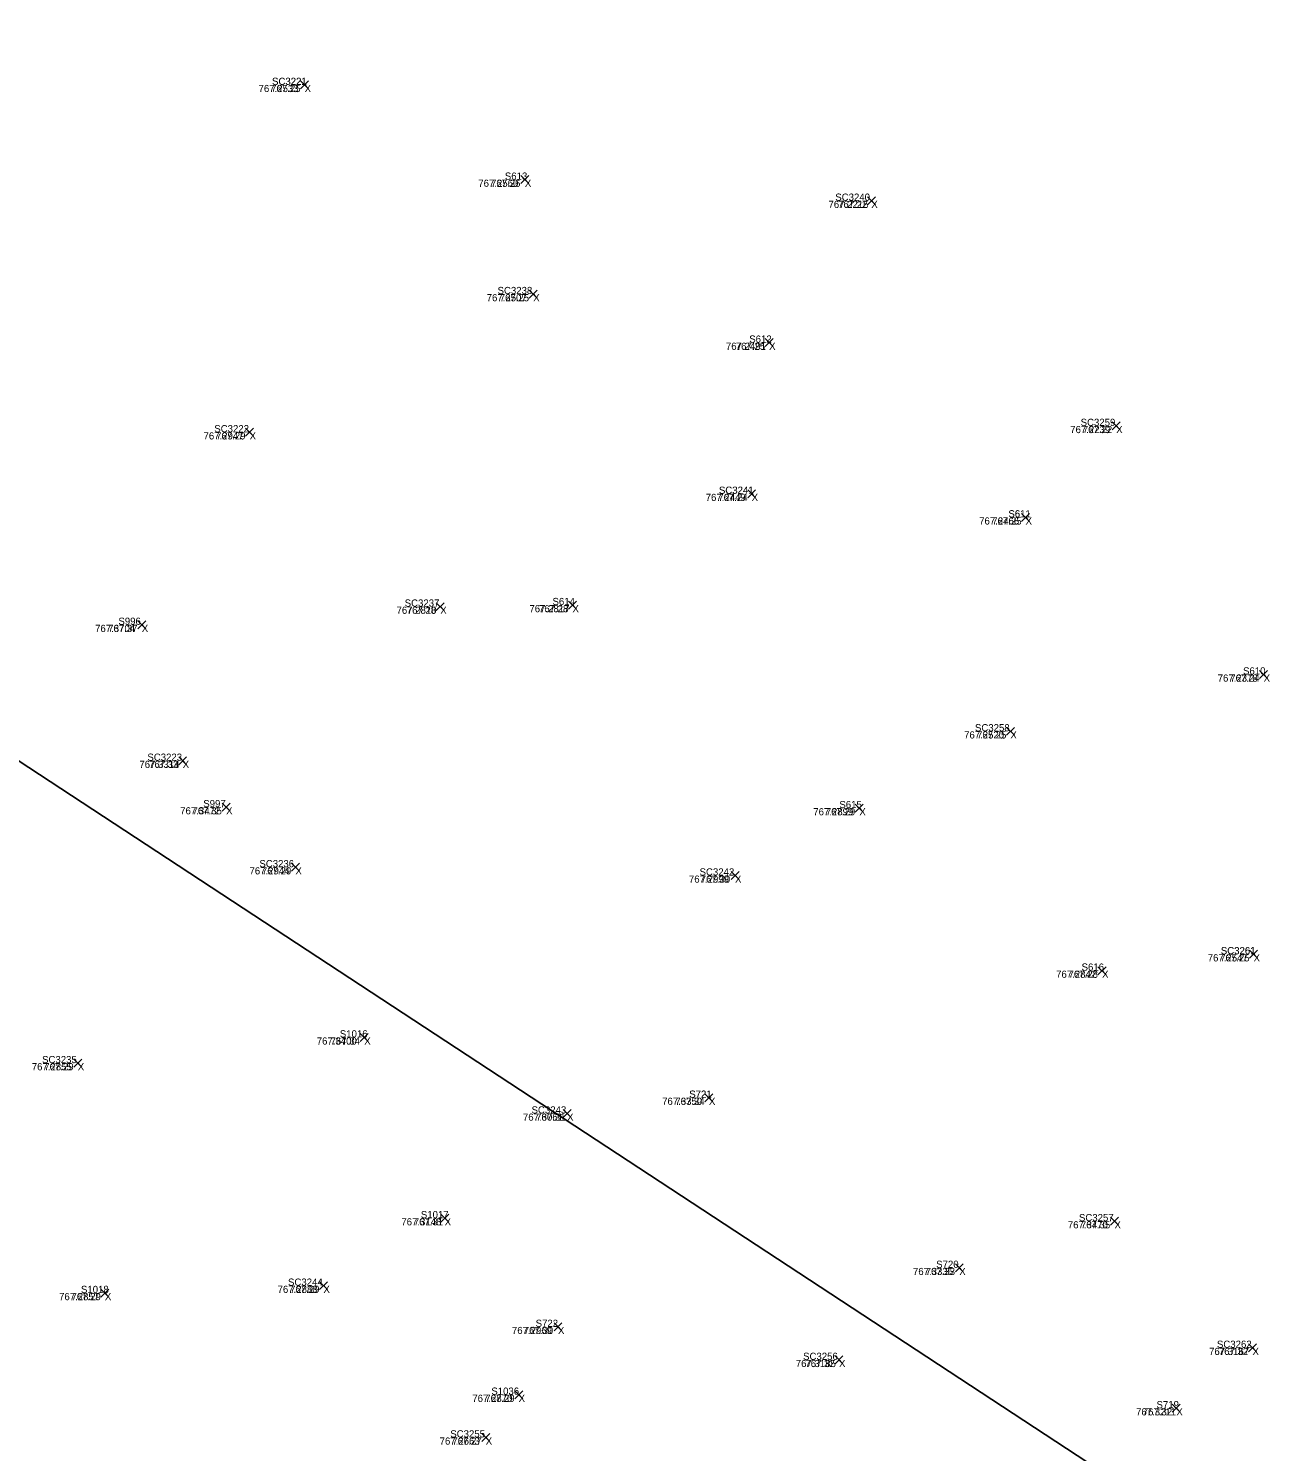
# Model space of a CAD drawing. Extents: x 1845019 to 1877956, y 680444 to 701081.
# Drawn here: x 1857714.75 to 1857725.26, y 694240.65 to 694252.54 of the extents above; entities that cross this region are included whole.
import ezdxf

# ---------------------------------------------------------------- set-up
doc = ezdxf.new("R2010")
doc.units = 0
for name, color, linetype in [('SV_X_CL_Survey_20', 7, 'Continuous'), ('SV_X_Random_Point', 7, 'Continuous'), ('SV_X_Text_Comment', 7, 'Continuous'), ('SV_X_Text_Elevation', 7, 'Continuous'), ('SV_X_Text_Name', 7, 'Continuous')]:
    doc.layers.add(name, color=color, linetype=linetype)

msp = doc.modelspace()

# ---------------------------------------------------------------- linework, layer by layer
at = {"layer": 'SV_X_CL_Survey_20'}
msp.add_line((1856038.267, 695346.314), (1858797.327, 693536.085), dxfattribs=at)
at = {"layer": 'SV_X_Random_Point'}
for p, q in [((1857717.021, 694252.038), (1857717.088, 694252.105)), ((1857717.021, 694252.105), (1857717.088, 694252.038)), ((1857717.021, 694252.038), (1857717.088, 694252.105)), ((1857717.021, 694252.105), (1857717.088, 694252.038)), ((1857718.862, 694251.247), (1857718.928, 694251.314)), ((1857718.862, 694251.314), (1857718.928, 694251.247)), ((1857718.862, 694251.247), (1857718.928, 694251.314)), ((1857718.862, 694251.314), (1857718.928, 694251.247)), ((1857721.757, 694251.071), (1857721.824, 694251.137)), ((1857721.757, 694251.137), (1857721.824, 694251.071)), ((1857721.757, 694251.071), (1857721.824, 694251.137)), ((1857721.757, 694251.137), (1857721.824, 694251.071)), ((1857718.931, 694250.29), (1857718.998, 694250.357)), ((1857718.931, 694250.357), (1857718.998, 694250.29)), ((1857718.931, 694250.29), (1857718.998, 694250.357)), ((1857718.931, 694250.357), (1857718.998, 694250.29)), ((1857720.903, 694249.885), (1857720.969, 694249.952)), ((1857720.903, 694249.952), (1857720.969, 694249.885)), ((1857720.903, 694249.885), (1857720.969, 694249.952)), ((1857720.903, 694249.952), (1857720.969, 694249.885)), ((1857716.561, 694249.136), (1857716.628, 694249.203)), ((1857716.561, 694249.203), (1857716.628, 694249.136)), ((1857716.561, 694249.136), (1857716.628, 694249.203)), ((1857716.561, 694249.203), (1857716.628, 694249.136)), ((1857723.802, 694249.189), (1857723.869, 694249.255)), ((1857723.802, 694249.255), (1857723.869, 694249.189)), ((1857723.802, 694249.189), (1857723.869, 694249.255)), ((1857723.802, 694249.255), (1857723.869, 694249.189)), ((1857720.757, 694248.621), (1857720.823, 694248.688)), ((1857720.757, 694248.688), (1857720.823, 694248.621)), ((1857720.757, 694248.621), (1857720.823, 694248.688)), ((1857720.757, 694248.688), (1857720.823, 694248.621)), ((1857723.046, 694248.424), (1857723.113, 694248.491)), ((1857723.046, 694248.491), (1857723.113, 694248.424)), ((1857723.046, 694248.424), (1857723.113, 694248.491)), ((1857723.046, 694248.491), (1857723.113, 694248.424)), ((1857718.155, 694247.679), (1857718.221, 694247.745)), ((1857718.155, 694247.745), (1857718.221, 694247.679)), ((1857718.155, 694247.679), (1857718.221, 694247.745)), ((1857718.155, 694247.745), (1857718.221, 694247.679)), ((1857719.259, 694247.692), (1857719.326, 694247.759)), ((1857719.259, 694247.759), (1857719.326, 694247.692)), ((1857719.259, 694247.692), (1857719.326, 694247.759)), ((1857719.259, 694247.759), (1857719.326, 694247.692)), ((1857715.66, 694247.527), (1857715.727, 694247.594)), ((1857715.66, 694247.594), (1857715.727, 694247.527)), ((1857715.66, 694247.527), (1857715.727, 694247.594)), ((1857715.66, 694247.594), (1857715.727, 694247.527)), ((1857725.034, 694247.112), (1857725.101, 694247.178)), ((1857725.034, 694247.178), (1857725.101, 694247.112)), ((1857725.034, 694247.112), (1857725.101, 694247.178)), ((1857725.034, 694247.178), (1857725.101, 694247.112)), ((1857722.919, 694246.637), (1857722.986, 694246.703)), ((1857722.919, 694246.703), (1857722.986, 694246.637)), ((1857722.919, 694246.637), (1857722.986, 694246.703)), ((1857722.919, 694246.703), (1857722.986, 694246.637)), ((1857716.003, 694246.39), (1857716.069, 694246.457)), ((1857716.003, 694246.457), (1857716.069, 694246.39)), ((1857716.003, 694246.39), (1857716.069, 694246.457)), ((1857716.003, 694246.457), (1857716.069, 694246.39)), ((1857716.366, 694246.002), (1857716.433, 694246.069)), ((1857716.366, 694246.069), (1857716.433, 694246.002)), ((1857716.366, 694246.002), (1857716.433, 694246.069)), ((1857716.366, 694246.069), (1857716.433, 694246.002)), ((1857721.656, 694245.995), (1857721.723, 694246.062)), ((1857721.656, 694246.062), (1857721.723, 694245.995)), ((1857721.656, 694245.995), (1857721.723, 694246.062)), ((1857721.656, 694246.062), (1857721.723, 694245.995)), ((1857716.944, 694245.5), (1857717.011, 694245.567)), ((1857716.944, 694245.567), (1857717.011, 694245.5)), ((1857716.944, 694245.5), (1857717.011, 694245.567)), ((1857716.944, 694245.567), (1857717.011, 694245.5)), ((1857720.618, 694245.431), (1857720.685, 694245.498)), ((1857720.618, 694245.498), (1857720.685, 694245.431)), ((1857720.618, 694245.431), (1857720.685, 694245.498)), ((1857720.618, 694245.498), (1857720.685, 694245.431)), ((1857724.951, 694244.773), (1857725.018, 694244.84)), ((1857724.951, 694244.84), (1857725.018, 694244.773)), ((1857724.951, 694244.773), (1857725.018, 694244.84)), ((1857724.951, 694244.84), (1857725.018, 694244.773)), ((1857723.684, 694244.636), (1857723.751, 694244.703)), ((1857723.684, 694244.703), (1857723.751, 694244.636)), ((1857723.684, 694244.636), (1857723.751, 694244.703)), ((1857723.684, 694244.703), (1857723.751, 694244.636)), ((1857717.519, 694244.079), (1857717.586, 694244.146)), ((1857717.519, 694244.146), (1857717.586, 694244.079)), ((1857717.519, 694244.079), (1857717.586, 694244.146)), ((1857717.519, 694244.146), (1857717.586, 694244.079)), ((1857715.125, 694243.864), (1857715.192, 694243.93)), ((1857715.125, 694243.93), (1857715.192, 694243.864)), ((1857715.125, 694243.864), (1857715.192, 694243.93)), ((1857715.125, 694243.93), (1857715.192, 694243.864)), ((1857720.399, 694243.575), (1857720.466, 694243.641)), ((1857720.399, 694243.641), (1857720.466, 694243.575)), ((1857720.399, 694243.575), (1857720.466, 694243.641)), ((1857720.399, 694243.641), (1857720.466, 694243.575)), ((1857719.214, 694243.443), (1857719.281, 694243.51)), ((1857719.214, 694243.51), (1857719.281, 694243.443)), ((1857719.214, 694243.443), (1857719.281, 694243.51)), ((1857719.214, 694243.51), (1857719.281, 694243.443)), ((1857718.192, 694242.568), (1857718.259, 694242.634)), ((1857718.192, 694242.634), (1857718.259, 694242.568)), ((1857718.192, 694242.568), (1857718.259, 694242.634)), ((1857718.192, 694242.634), (1857718.259, 694242.568)), ((1857723.788, 694242.542), (1857723.855, 694242.609)), ((1857723.788, 694242.609), (1857723.855, 694242.542)), ((1857723.788, 694242.542), (1857723.855, 694242.609)), ((1857723.788, 694242.609), (1857723.855, 694242.542)), ((1857722.492, 694242.153), (1857722.558, 694242.22)), ((1857722.492, 694242.22), (1857722.558, 694242.153)), ((1857722.492, 694242.153), (1857722.558, 694242.22)), ((1857722.492, 694242.22), (1857722.558, 694242.153)), ((1857717.179, 694242.004), (1857717.246, 694242.07)), ((1857717.179, 694242.07), (1857717.246, 694242.004)), ((1857717.179, 694242.004), (1857717.246, 694242.07)), ((1857717.179, 694242.07), (1857717.246, 694242.004)), ((1857715.353, 694241.942), (1857715.42, 694242.009)), ((1857715.353, 694242.009), (1857715.42, 694241.942)), ((1857715.353, 694241.942), (1857715.42, 694242.009)), ((1857715.353, 694242.009), (1857715.42, 694241.942)), ((1857719.139, 694241.66), (1857719.205, 694241.727)), ((1857719.139, 694241.727), (1857719.205, 694241.66)), ((1857719.139, 694241.66), (1857719.205, 694241.727)), ((1857719.139, 694241.727), (1857719.205, 694241.66)), ((1857724.941, 694241.485), (1857725.008, 694241.551)), ((1857724.941, 694241.551), (1857725.008, 694241.485)), ((1857724.941, 694241.485), (1857725.008, 694241.551)), ((1857724.941, 694241.551), (1857725.008, 694241.485)), ((1857721.487, 694241.384), (1857721.553, 694241.45)), ((1857721.487, 694241.45), (1857721.553, 694241.384)), ((1857721.487, 694241.384), (1857721.553, 694241.45)), ((1857721.487, 694241.45), (1857721.553, 694241.384)), ((1857718.81, 694241.092), (1857718.877, 694241.159)), ((1857718.81, 694241.159), (1857718.877, 694241.092)), ((1857718.81, 694241.092), (1857718.877, 694241.159)), ((1857718.81, 694241.159), (1857718.877, 694241.092)), ((1857724.305, 694240.98), (1857724.372, 694241.046)), ((1857724.305, 694241.046), (1857724.372, 694240.98)), ((1857724.305, 694240.98), (1857724.372, 694241.046)), ((1857724.305, 694241.046), (1857724.372, 694240.98)), ((1857718.535, 694240.736), (1857718.602, 694240.803)), ((1857718.535, 694240.803), (1857718.602, 694240.736)), ((1857718.535, 694240.736), (1857718.602, 694240.803)), ((1857718.535, 694240.803), (1857718.602, 694240.736))]:
    msp.add_line(p, q, dxfattribs=at)

# ---------------------------------------------------------------- texts
at = {"layer": 'SV_X_Text_Comment'}
for p in [(1857717.055, 694252.012), (1857718.895, 694251.22), (1857721.79, 694251.044), (1857718.965, 694250.264), (1857720.936, 694249.858), (1857716.595, 694249.109), (1857723.836, 694249.162), (1857720.79, 694248.595), (1857723.079, 694248.398), (1857719.293, 694247.665), (1857718.188, 694247.652), (1857715.694, 694247.5), (1857725.068, 694247.085), (1857722.952, 694246.61), (1857716.036, 694246.364), (1857716.399, 694245.976), (1857721.69, 694245.968), (1857716.978, 694245.474), (1857720.651, 694245.405), (1857724.984, 694244.747), (1857723.718, 694244.61), (1857717.553, 694244.052), (1857715.159, 694243.837), (1857720.433, 694243.548), (1857719.248, 694243.416), (1857718.225, 694242.541), (1857723.822, 694242.516), (1857722.525, 694242.126), (1857717.212, 694241.977), (1857715.386, 694241.916), (1857719.172, 694241.633), (1857724.975, 694241.458), (1857721.52, 694241.357), (1857718.843, 694241.066), (1857724.339, 694240.953), (1857718.568, 694240.709)]:
    msp.add_text('X', height=0.06, dxfattribs=at).set_placement(p)
at = {"layer": 'SV_X_Text_Elevation'}
for s, p in [('767.2533', (1857716.67, 694252.012)), ('767.25', (1857716.775, 694252.012)), ('767.2560', (1857718.506, 694251.22)), ('767.26', (1857718.612, 694251.22)), ('767.2215', (1857721.432, 694251.044)), ('767.22', (1857721.512, 694251.044)), ('767.2507', (1857718.576, 694250.264)), ('767.25', (1857718.685, 694250.264)), ('767.2491', (1857720.575, 694249.858)), ('767.25', (1857720.657, 694249.858)), ('767.2947', (1857716.21, 694249.109)), ('767.29', (1857716.315, 694249.109)), ('767.2239', (1857723.452, 694249.162)), ('767.22', (1857723.557, 694249.162)), ('767.2449', (1857720.406, 694248.595)), ('767.24', (1857720.511, 694248.595)), ('767.2466', (1857722.691, 694248.398)), ('767.25', (1857722.8, 694248.398)), ('767.2817', (1857718.933, 694247.665)), ('767.28', (1857719.013, 694247.665)), ('767.2810', (1857717.823, 694247.652)), ('767.28', (1857717.908, 694247.652)), ('767.3704', (1857715.304, 694247.5)), ('767.37', (1857715.413, 694247.5)), ('767.2378', (1857724.684, 694247.085)), ('767.24', (1857724.789, 694247.085)), ('767.2520', (1857722.565, 694246.61)), ('767.25', (1857722.673, 694246.61)), ('767.3314', (1857715.674, 694246.364)), ('767.33', (1857715.755, 694246.364)), ('767.3472', (1857716.015, 694245.976)), ('767.35', (1857716.118, 694245.976)), ('767.2899', (1857721.305, 694245.968)), ('767.29', (1857721.41, 694245.968)), ('767.2944', (1857716.594, 694245.474)), ('767.29', (1857716.698, 694245.474)), ('767.2999', (1857720.266, 694245.405)), ('767.30', (1857720.365, 694245.405)), ('767.2547', (1857724.601, 694244.747)), ('767.25', (1857724.705, 694244.747)), ('767.2842', (1857723.334, 694244.61)), ('767.28', (1857723.438, 694244.61)), ('767.3400', (1857717.156, 694244.052)), ('767.34', (1857717.272, 694244.052)), ('767.2855', (1857714.775, 694243.837)), ('767.29', (1857714.879, 694243.837)), ('767.3350', (1857720.042, 694243.548)), ('767.34', (1857720.152, 694243.548)), ('767.3061', (1857718.879, 694243.416)), ('767.31', (1857718.989, 694243.416)), ('767.3148', (1857717.863, 694242.541)), ('767.31', (1857717.967, 694242.541)), ('767.3470', (1857723.432, 694242.516)), ('767.35', (1857723.541, 694242.516)), ('767.3335', (1857722.138, 694242.126)), ('767.33', (1857722.244, 694242.126)), ('767.2888', (1857716.829, 694241.977)), ('767.29', (1857716.933, 694241.977)), ('767.2857', (1857715.003, 694241.916)), ('767.29', (1857715.107, 694241.916)), ('767.2969', (1857718.787, 694241.633)), ('767.30', (1857718.886, 694241.633)), ('767.3167', (1857724.612, 694241.458)), ('767.32', (1857724.694, 694241.458)), ('767.3185', (1857721.159, 694241.357)), ('767.32', (1857721.239, 694241.357)), ('767.2870', (1857718.456, 694241.066)), ('767.29', (1857718.564, 694241.066)), ('767.3211', (1857724.002, 694240.953)), ('767.32', (1857724.058, 694240.953)), ('767.2663', (1857718.183, 694240.709)), ('767.27', (1857718.289, 694240.709))]:
    msp.add_text(s, height=0.06, dxfattribs=at).set_placement(p)
at = {"layer": 'SV_X_Text_Name'}
for s, p in [('SC3221', (1857716.782, 694252.072)), ('SC3221', (1857716.783, 694252.072)), ('S613', (1857718.728, 694251.28)), ('S613', (1857718.728, 694251.28)), ('SC3240', (1857721.489, 694251.104)), ('SC3240', (1857721.489, 694251.104)), ('SC3238', (1857718.667, 694250.324)), ('SC3238', (1857718.667, 694250.324)), ('S612', (1857720.77, 694249.918)), ('S612', (1857720.77, 694249.918)), ('SC3259', (1857723.539, 694249.222)), ('SC3259', (1857723.539, 694249.222)), ('SC3222', (1857716.3, 694249.169)), ('SC3222', (1857716.3, 694249.169)), ('SC3241', (1857720.516, 694248.655)), ('SC3241', (1857720.517, 694248.655)), ('S611', (1857722.935, 694248.458)), ('S611', (1857722.936, 694248.458)), ('SC3237', (1857717.891, 694247.712)), ('SC3237', (1857717.891, 694247.712)), ('S614', (1857719.126, 694247.725)), ('S614', (1857719.126, 694247.725)), ('S996', (1857715.499, 694247.56)), ('S996', (1857715.499, 694247.56)), ('S610', (1857724.896, 694247.145)), ('S610', (1857724.896, 694247.145)), ('SC3258', (1857722.656, 694246.67)), ('SC3258', (1857722.656, 694246.67)), ('SC3223', (1857715.741, 694246.424)), ('SC3223', (1857715.741, 694246.424)), ('S997', (1857716.208, 694246.036)), ('S997', (1857716.208, 694246.036)), ('S615', (1857721.523, 694246.028)), ('S615', (1857721.523, 694246.028)), ('SC3236', (1857716.677, 694245.534)), ('SC3236', (1857716.677, 694245.534)), ('SC3242', (1857720.355, 694245.465)), ('SC3242', (1857720.355, 694245.465)), ('SC3261', (1857724.71, 694244.807)), ('SC3261', (1857724.711, 694244.807)), ('S616', (1857723.547, 694244.67)), ('S616', (1857723.547, 694244.67)), ('S1016', (1857717.349, 694244.112)), ('S1016', (1857717.349, 694244.112)), ('SC3235', (1857714.861, 694243.897)), ('SC3235', (1857714.861, 694243.897)), ('S721', (1857720.268, 694243.608)), ('S721', (1857720.269, 694243.608)), ('SC3243', (1857718.951, 694243.476)), ('SC3243', (1857718.951, 694243.476)), ('S1017', (1857718.026, 694242.601)), ('S1017', (1857718.026, 694242.601)), ('SC3257', (1857723.525, 694242.576)), ('SC3257', (1857723.525, 694242.576)), ('S720', (1857722.332, 694242.186)), ('S720', (1857722.332, 694242.186)), ('S1018', (1857715.186, 694241.976)), ('S1018', (1857715.186, 694241.976)), ('SC3244', (1857716.916, 694242.037)), ('SC3244', (1857716.916, 694242.037)), ('S722', (1857718.985, 694241.693)), ('S722', (1857718.985, 694241.693)), ('SC3262', (1857724.678, 694241.518)), ('SC3262', (1857724.678, 694241.518)), ('SC3256', (1857721.22, 694241.417)), ('SC3256', (1857721.22, 694241.417)), ('S1036', (1857718.615, 694241.126)), ('S1036', (1857718.615, 694241.126)), ('S719', (1857724.173, 694241.013)), ('S719', (1857724.173, 694241.013)), ('SC3255', (1857718.272, 694240.769)), ('SC3255', (1857718.272, 694240.769))]:
    msp.add_text(s, height=0.06, dxfattribs=at).set_placement(p)

doc.saveas('drawing.dxf')
